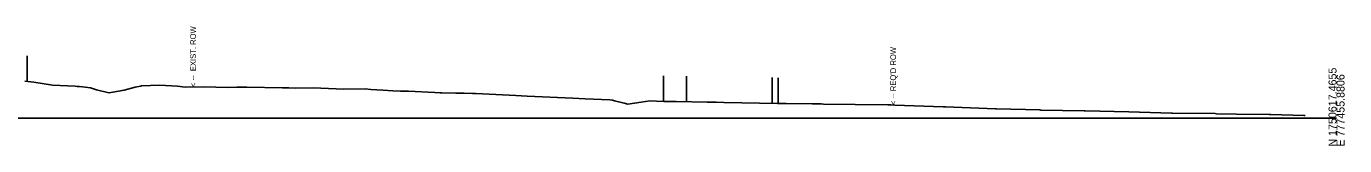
# Model space of a CAD drawing. Extents: x 776426 to 854588, y 1736205 to 1756790.
# Drawn here: x 805212.5 to 805673.6, y 1753205.1 to 1753247 of the extents above; entities that cross this region are included whole.
import ezdxf

# ---------------------------------------------------------------- set-up
doc = ezdxf.new("R2010")
doc.units = 0
for name, color, linetype in [('63', 7, 'Continuous'), ('DTM CONTOURS_MAJOR_TX', 7, 'Continuous'), ('DTM_X_FLOW_ARROWS', 7, 'Continuous'), ('TRANS_EOP_PAVED', 7, 'Continuous'), ('TRANS_UNPAVED_SHOULDERS', 7, 'Continuous'), ('XS_P_ROW', 7, 'Continuous'), ('XS_X_ROW', 7, 'Continuous')]:
    doc.layers.add(name, color=color, linetype=linetype)

msp = doc.modelspace()

# ---------------------------------------------------------------- linework, layer by layer
at = {"layer": '63'}
msp.add_line((805212.79, 1753236.61), (805212.79, 1753227.61), dxfattribs=at)
msp.add_line((805212.79, 1753236.61), (805212.79, 1753227.61), dxfattribs=at)
at = {"layer": 'DTM CONTOURS_MAJOR_TX'}
msp.add_line((805170.79, 1753214.76), (805670.79, 1753214.76), dxfattribs=at)
at = {"layer": 'DTM_X_FLOW_ARROWS'}
msp.add_lwpolyline([(805211.98, 1753227.7), (805215.07, 1753227.33), (805221.63, 1753226.36), (805229.51, 1753225.96), (805230.29, 1753225.88), (805231.04, 1753225.88), (805232.14, 1753225.7), (805234.92, 1753225.43), (805236.96, 1753224.72), (805240.79, 1753223.77), (805241.39, 1753223.63), (805242.75, 1753223.87), (805246.62, 1753224.61), (805250.51, 1753225.56), (805252.4, 1753226), (805252.7, 1753226.02), (805259.05, 1753226.35), (805263.23, 1753226.13), (805265.34, 1753225.95), (805268.02, 1753225.63), (805274.57, 1753225.68), (805282.96, 1753225.5), (805286.08, 1753225.63), (805287.92, 1753225.64), (805289.59, 1753225.58), (805302.08, 1753225.42), (805304.28, 1753225.35), (805306.45, 1753225.28), (805312.82, 1753225.33), (805323.49, 1753224.95), (805331.01, 1753224.98), (805332.95, 1753224.76), (805337.11, 1753224.59), (805340.61, 1753224.33), (805343.34, 1753224.23), (805346.11, 1753224.16), (805355.32, 1753223.72), (805357.22, 1753223.64), (805357.85, 1753223.62), (805362.69, 1753223.49), (805365.67, 1753223.45), (805368.48, 1753223.35), (805369.23, 1753223.38), (805369.69, 1753223.37), (805383.75, 1753222.67), (805387.65, 1753222.43), (805403.69, 1753221.71), (805408, 1753221.49), (805416.57, 1753221.22), (805417.5, 1753221.03), (805418.25, 1753220.82), (805421.6, 1753220.03), (805422.89, 1753219.67), (805427.54, 1753220.39), (805430.54, 1753220.76), (805432.86, 1753220.7), (805435.51, 1753220.61), (805437.16, 1753220.62), (805439.8, 1753220.58), (805450.59, 1753220.35), (805451.45, 1753220.34), (805452.15, 1753220.33), (805453.72, 1753220.32), (805456.41, 1753220.27), (805475.26, 1753219.92), (805478.31, 1753219.88), (805487.33, 1753219.75), (805490.45, 1753219.72), (805491.36, 1753219.68), (805502.43, 1753219.53), (805513.82, 1753219.37), (805514.89, 1753219.38), (805516.25, 1753219.34), (805533.24, 1753218.69), (805534.04, 1753218.65), (805536.95, 1753218.55), (805542.78, 1753218.35), (805551.48, 1753218.05), (805551.9, 1753218.04), (805567.04, 1753217.6), (805567.38, 1753217.59), (805582.46, 1753217.31), (805582.85, 1753217.3), (805598.09, 1753216.96), (805613.01, 1753216.54), (805613.44, 1753216.53), (805628.32, 1753216.32), (805628.84, 1753216.3), (805635.85, 1753216.11), (805647.28, 1753216), (805647.84, 1753215.98), (805659.3, 1753215.7), (805659.84, 1753215.68)], dxfattribs=at)
at = {"layer": 'TRANS_EOP_PAVED'}
for p, q in [((805443.35, 1753229.51), (805443.35, 1753220.51)), ((805443.35, 1753229.51), (805443.35, 1753220.51)), ((805473.34, 1753228.96), (805473.34, 1753219.96)), ((805473.34, 1753228.96), (805473.34, 1753219.96))]:
    msp.add_line(p, q, dxfattribs=at)
at = {"layer": 'TRANS_UNPAVED_SHOULDERS'}
for p, q in [((805435.31, 1753229.62), (805435.31, 1753220.62)), ((805435.31, 1753229.62), (805435.31, 1753220.62)), ((805475.51, 1753228.92), (805475.51, 1753219.92)), ((805475.51, 1753228.92), (805475.51, 1753219.92))]:
    msp.add_line(p, q, dxfattribs=at)

# ---------------------------------------------------------------- texts
at = {"layer": 'DTM CONTOURS_MAJOR_TX'}
for s, p in [('N 1750617.4655', (805670.79, 1753204.76)), ('E 777455.8806', (805673.59, 1753204.76))]:
    msp.add_text(s, height=2.8, rotation=90, dxfattribs=at).set_placement(p)
at = {"layer": 'XS_P_ROW'}
msp.add_text("< -- REQ'D ROW", height=2, rotation=90, dxfattribs=at).set_placement((805516.7, 1753219.36))
at = {"layer": 'XS_X_ROW'}
msp.add_text('< --  EXIST. ROW', height=2, rotation=90, dxfattribs=at).set_placement((805271.79, 1753225.65))

doc.saveas('drawing.dxf')
